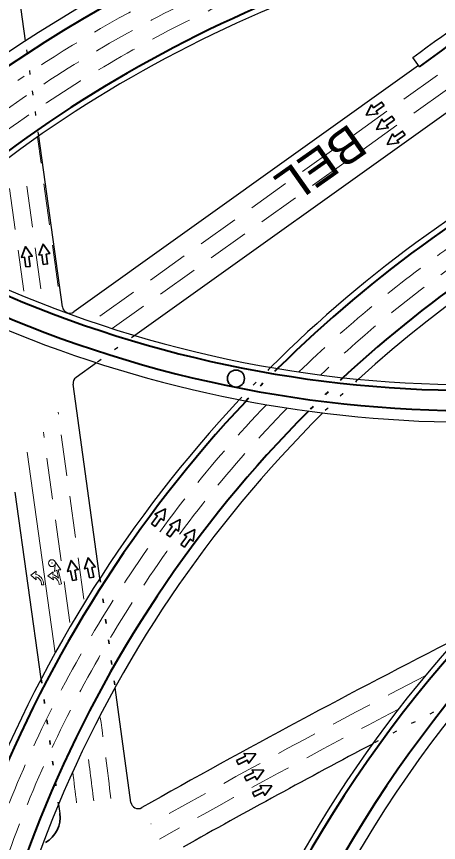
# Model space of a CAD drawing. Extents: x 2329387 to 2347382, y 6951580 to 6987999.
# Drawn here: x 2332304 to 2332597, y 6964055 to 6964628 of the extents above; entities that cross this region are included whole.
import ezdxf

# ---------------------------------------------------------------- set-up
doc = ezdxf.new("R2010")
doc.units = 0
doc.header["$LTSCALE"] = 9.6
doc.header["$PDMODE"] = 32
doc.header["$PDSIZE"] = 4.8
doc.linetypes.add('DOTTED', pattern=[1.5, 0.3, -1.2])
doc.linetypes.add('MEDIUM_DASHED', pattern=[4.5, 3, -1.5])
for name, color, linetype, lineweight in [('27', 7, 'Continuous', 40), ('28', 7, 'Continuous', 25), ('29', 7, 'DOTTED', 35), ('30', 7, 'Continuous', 13), ('41', 7, 'Continuous', 35), ('50', 7, 'MEDIUM_DASHED', 13)]:
    doc.layers.add(name, color=color, linetype=linetype, lineweight=lineweight)
doc.layers.add('40', color=7, linetype='Continuous')

msp = doc.modelspace()

# ---------------------------------------------------------------- linework, layer by layer
at = {"layer": '27', "lineweight": 25}
msp.add_line((2332583.746, 6964593.575), (2332579.094, 6964600.084), dxfattribs=at)
at = {"layer": '27'}
for centre, radius, start, end in [((2339406.145, 6959556.474), 7976, 170.51466, 170.51466), ((2332620.068, 6965189.757), 835, 186.84922, 291.74312), ((2332620.068, 6965189.757), 821, 186.84892, 289.1959), ((2332663.723, 6963948.074), 881.473, 95.26524, 133.00988), ((2332663.723, 6963948.074), 857.473, 95.26524, 132.87538), ((2332823.658, 6963822.838), 933, 94.37248, 124.27186), ((2332823.658, 6963822.838), 885, 94.37248, 132.56707), ((2330918.053, 6966924.345), 2864.789, 305.55163, 307.55163), ((2333105.715, 6963757.74), 881.473, 98.35573, 134.73223), ((2333105.715, 6963757.74), 845.473, 98.35522, 132.84387), ((2333243.898, 6963625.567), 849, 109.23607, 171.39072), ((2333254.585, 6963629.346), 835, 109.47521, 171.39072), ((2333105.715, 6963757.74), 881.473, 136.77426, 179.92799), ((2333105.715, 6963757.74), 845.473, 135.11174, 179.92799)]:
    msp.add_arc(centre, radius, start, end, dxfattribs=at)
at = {"layer": '27', "lineweight": 25}
for centre, radius, start, end in [((2332663.723, 6963948.074), 889.473, 95.26524, 133.04292), ((2332663.723, 6963948.074), 853.473, 95.26524, 132.84756), ((2332823.658, 6963822.838), 941, 94.37248, 124.27186), ((2332823.658, 6963822.838), 881, 94.37248, 132.47918), ((2330918.053, 6966924.345), 2856.789, 305.55163, 307.55163), ((2333105.715, 6963757.74), 885.473, 98.35573, 134.91734), ((2333105.715, 6963757.74), 837.473, 98.35584, 132.36198), ((2332620.068, 6965189.757), 817, 237.98047, 289.1959), ((2332620.068, 6965189.757), 843, 237.06532, 283.52428), ((2333254.585, 6963629.346), 827, 109.47521, 171.39072), ((2333105.715, 6963757.74), 885.473, 136.93809, 179.70414), ((2333243.898, 6963625.567), 853, 119.81577, 171.39072), ((2333105.715, 6963757.74), 837.473, 134.69052, 179.92799)]:
    msp.add_arc(centre, radius, start, end, dxfattribs=at)
at = {"layer": '27', "linetype": 'DOTTED', "lineweight": 25}
for radius, start, end in [(885.473, 134.91735, 136.93809), (837.473, 132.36198, 134.69052)]:
    msp.add_arc((2333105.715, 6963757.74), radius, start, end, dxfattribs=at)
at = {"layer": '27', "linetype": 'DOTTED'}
for radius, start, end in [(881.473, 134.73223, 136.77426), (845.473, 132.84387, 135.11175)]:
    msp.add_arc((2333105.715, 6963757.74), radius, start, end, dxfattribs=at)
at = {"layer": '28'}
for p, q in [((2332310.449, 6964611.57), (2332295.71, 6964718.128)), ((2332583.164, 6964594.389), (2332343.871, 6964423.377)), ((2332645.928, 6964592.537), (2332386.223, 6964406.938)), ((2332336.011, 6964426.76), (2332319.602, 6964545.395)), ((2332359.69, 6964387.976), (2332345.483, 6964377.823)), ((2332362.063, 6964238.411), (2332343.437, 6964373.07)), ((2332321.262, 6964168.466), (2332303.321, 6964298.171)), ((2332383.598, 6964082.718), (2332372.56, 6964162.518)), ((2332333.306, 6964081.385), (2332334.192, 6964074.984))]:
    msp.add_line(p, q, dxfattribs=at)
at = {"layer": '28', "linetype": 'DOTTED'}
for p, q in [((2332319.602, 6964545.395), (2332310.379, 6964612.078)), ((2332386.223, 6964406.938), (2332359.69, 6964387.976))]:
    msp.add_line(p, q, dxfattribs=at)
at = {"layer": '28'}
for centre, radius, start, end in [((2332340.964, 6964427.445), 5, 187.87499, 305.55163), ((2332348.39, 6964373.755), 5, 125.55163, 187.87499), ((2335226.842, 6959057.955), 5766.57, 116.98298, 119.45706), ((2335226.842, 6959057.955), 5728.57, 117.84512, 119.34001), ((2332388.551, 6964083.403), 5, 187.87499, 299.45706)]:
    msp.add_arc(centre, radius, start, end, dxfattribs=at)
at = {"layer": '28', "linetype": 'DOTTED'}
msp.add_arc((2335226.842, 6959057.955), 5728.57, 117.07917, 117.84512, dxfattribs=at)
at = {"layer": '28', "lineweight": 35}
msp.add_arc((2332314.38, 6964072.244), 20, 299.69572, 7.87499, dxfattribs=at)
at = {"layer": '29'}
for p, q in [((2332362.063, 6964238.411), (2332372.56, 6964162.518)), ((2332321.262, 6964168.466), (2332333.306, 6964081.385))]:
    msp.add_line(p, q, dxfattribs=at)
at = {"layer": '30'}
for points in [[(2332333.376, 6964238.349), (2332332.051, 6964243.956), (2332330.411, 6964243.074), (2332331.25, 6964249.438)], [(2332331.25, 6964249.438), (2332334.847, 6964244.122), (2332332.986, 6964244.175), (2332335.279, 6964234.462), (2332333.762, 6964234.104), (2332333.432, 6964235.496)], [(2332314.144, 6964240.535), (2332317.906, 6964243.275), (2332317.654, 6964240.964)], [(2332317.515, 6964239.394), (2332317.789, 6964237.251), (2332314.144, 6964240.535)], [(2332329.387, 6964239.401), (2332329.883, 6964237.299), (2332325.79, 6964240.011), (2332329.554, 6964242.872), (2332329.305, 6964240.668)], [(2332322.915, 6964235.327), (2332323.098, 6964233.898), (2332321.551, 6964233.701), (2332321.389, 6964234.962)]]:
    msp.add_lwpolyline(points, dxfattribs=at)
for centre, radius, start, end in [((2332316.153, 6964234.292), 6.84, 8.69422, 77.30283), ((2332328.372, 6964234.302), 6.436, 38.97755, 81.66158), ((2332316.153, 6964234.292), 5.28, 7.29331, 75.04404), ((2332328.372, 6964234.302), 5.2, 13.28676, 78.74277)]:
    msp.add_arc(centre, radius, start, end, dxfattribs=at)
msp.add_point((2332328.721, 6964248.839), dxfattribs=at)
at = {"layer": '41'}
for points in [[(2332559.24, 6964566.578), (2332557.509, 6964569.029), (2332551.949, 6964565.102), (2332550.543, 6964567.093), (2332546.842, 6964559.853), (2332554.903, 6964560.92), (2332553.68, 6964562.651)], [(2332566.431, 6964556.698), (2332564.7, 6964559.149), (2332559.14, 6964555.222), (2332557.734, 6964557.213), (2332554.033, 6964549.973), (2332562.094, 6964551.04), (2332560.871, 6964552.771)], [(2332573.812, 6964546.38), (2332572.081, 6964548.832), (2332566.521, 6964544.905), (2332565.115, 6964546.896), (2332561.414, 6964539.655), (2332569.475, 6964540.722), (2332568.252, 6964542.454)], [(2332322.72, 6964456.304), (2332325.695, 6964456.694), (2332324.811, 6964463.443), (2332327.228, 6964463.76), (2332322.546, 6964470.408), (2332319.734, 6964462.778), (2332321.836, 6964463.053)], [(2332310.628, 6964454.544), (2332313.603, 6964454.934), (2332312.719, 6964461.683), (2332315.136, 6964462), (2332310.454, 6964468.648), (2332307.642, 6964461.018), (2332309.744, 6964461.293)], [(2332397.916, 6964276.136), (2332400.349, 6964274.379), (2332404.334, 6964279.897), (2332406.31, 6964278.47), (2332407.462, 6964286.519), (2332400.183, 6964282.895), (2332401.902, 6964281.654)], [(2332408.245, 6964268.77), (2332410.678, 6964267.013), (2332414.663, 6964272.531), (2332416.639, 6964271.104), (2332417.791, 6964279.154), (2332410.512, 6964275.529), (2332412.23, 6964274.288)], [(2332418.252, 6964261.758), (2332420.685, 6964260.001), (2332424.67, 6964265.519), (2332426.646, 6964264.092), (2332427.799, 6964272.142), (2332420.52, 6964268.517), (2332422.238, 6964267.276)], [(2332354.761, 6964238.561), (2332357.709, 6964239.117), (2332356.449, 6964245.806), (2332358.844, 6964246.257), (2332353.796, 6964252.633), (2332351.417, 6964244.857), (2332353.5, 6964245.25)], [(2332342.945, 6964236.704), (2332345.893, 6964237.26), (2332344.633, 6964243.948), (2332347.028, 6964244.4), (2332341.981, 6964250.776), (2332339.601, 6964243), (2332341.684, 6964243.393)], [(2332456.841, 6964111.792), (2332458.15, 6964109.092), (2332464.275, 6964112.061), (2332465.338, 6964109.868), (2332470.168, 6964116.41), (2332462.041, 6964116.669), (2332462.965, 6964114.761)], [(2332462.445, 6964100.411), (2332463.754, 6964097.711), (2332469.878, 6964100.68), (2332470.942, 6964098.487), (2332475.772, 6964105.029), (2332467.644, 6964105.288), (2332468.569, 6964103.38)], [(2332467.933, 6964089.493), (2332469.242, 6964086.793), (2332475.367, 6964089.763), (2332476.43, 6964087.569), (2332481.26, 6964094.111), (2332473.133, 6964094.37), (2332474.057, 6964092.463)]]:
    msp.add_lwpolyline(points, close=True, dxfattribs=at)
at = {"layer": '50'}
for p, q in [((2332631.392, 6964612.877), (2332356.514, 6964416.434)), ((2332638.37, 6964603.114), (2332370.624, 6964411.768)), ((2332333.027, 6964441.033), (2332318.681, 6964544.752)), ((2332309.254, 6964437.745), (2332297.63, 6964521.785)), ((2332321.141, 6964439.389), (2332310.492, 6964516.374)), ((2332350.942, 6964223.928), (2332332.999, 6964353.657)), ((2332341.081, 6964207.643), (2332322.817, 6964339.687))]:
    msp.add_line(p, q, dxfattribs=at)
at = {"layer": '50', "linetype": 'Continuous'}
msp.add_line((2332330.899, 6964186.37), (2332311.612, 6964325.812), dxfattribs=at)
at = {"layer": '50', "linetype": 'Continuous', "lineweight": 35}
msp.add_circle((2332456.463, 6964377.007), 5.904, dxfattribs=at)
at = {"layer": '50'}
for centre, radius, start, end in [((2332663.723, 6963948.074), 869.473, 95.26524, 132.94943), ((2332823.658, 6963822.838), 921, 94.37248, 124.27186), ((2332823.658, 6963822.838), 909, 94.37248, 133.04726), ((2332823.658, 6963822.838), 897, 94.37248, 132.81701), ((2333105.715, 6963757.74), 869.473, 98.3562, 134.14917), ((2333105.715, 6963757.74), 857.473, 98.35615, 133.5213), ((2333105.715, 6963757.74), 869.473, 136.25913, 179.92799), ((2333105.715, 6963757.74), 857.473, 135.70613, 179.92799), ((2335226.842, 6959057.955), 5753.57, 117.30332, 119.45706), ((2335226.842, 6959057.955), 5741.57, 117.57389, 119.45706), ((2329538.033, 6963746.549), 2851.789, 6.82255, 7.963), ((2329538.033, 6963746.549), 2839.789, 6.82255, 7.61908)]:
    msp.add_arc(centre, radius, start, end, dxfattribs=at)
at = {"layer": '50', "linetype": 'Continuous'}
msp.add_arc((2329538.033, 6963746.549), 2827.789, 6.82255, 7.26068, dxfattribs=at)

# ---------------------------------------------------------------- texts
at = {"layer": '40', "width": 1.1}
msp.add_text('BEL', height=24, rotation=215.196, dxfattribs=at).set_placement((2332535.599, 6964554.797))

doc.saveas('drawing.dxf')
